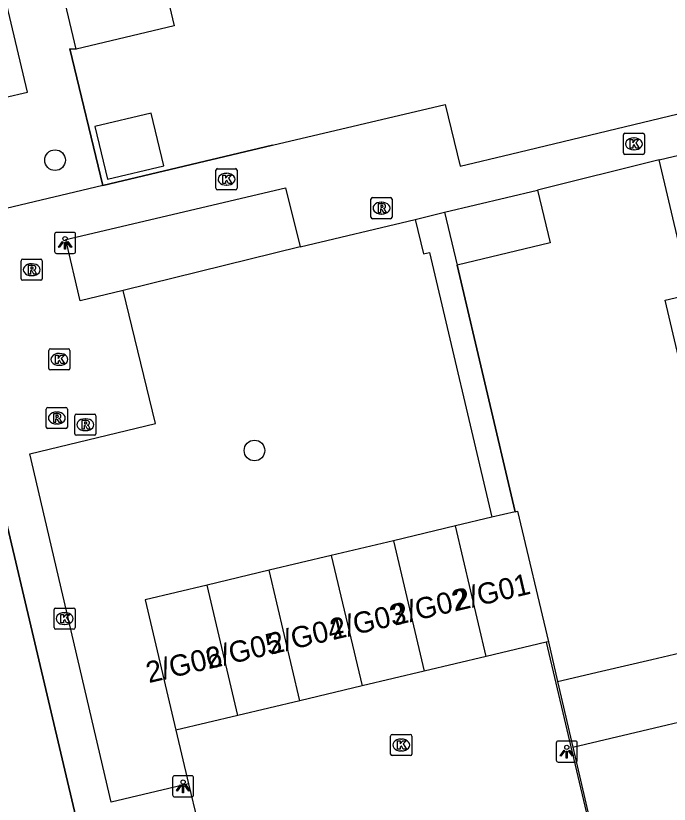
# Model space of a CAD drawing. Extents: x 157663 to 158496, y 379212 to 380934.
# Drawn here: x 158321.09 to 158352, y 380744.87 to 380782.15 of the extents above; entities that cross this region are included whole.
import ezdxf

# ---------------------------------------------------------------- set-up
doc = ezdxf.new("R2010")
doc.units = 0
for name, color, linetype in [('IMGEO_Boom', 7, 'Continuous'), ('IMGEO_Groenvoorziening', 7, 'Continuous'), ('IMGEO_Hek', 7, 'Continuous'), ('IMGEO_Kolk', 7, 'Continuous'), ('IMGEO_Lichtpunt', 7, 'Continuous'), ('IMGEO_Muur', 7, 'Continuous'), ('IMGEO_Pand', 7, 'Continuous'), ('IMGEO_Pand_nummerreeks', 7, 'Continuous'), ('IMGEO_Rijbaan_lokaal_open', 7, 'Continuous'), ('IMGEO_Rioolput', 7, 'Continuous'), ('IMGEO_Voetpad_open', 7, 'Continuous')]:
    doc.layers.add(name, color=color, linetype=linetype)

msp = doc.modelspace()

# ---------------------------------------------------------------- linework, layer by layer
at = {"layer": 'IMGEO_Boom'}
for centre in [(158322.952, 380775.321), (158332.384, 380761.593)]:
    msp.add_circle(centre, 0.489, dxfattribs=at)
at = {"layer": 'IMGEO_Groenvoorziening'}
for points in [[(158323.949, 380780.572), (158323.65, 380780.585), (158325.212, 380774.131)], [(158334.541, 380771.23), (158326.174, 380769.159)]]:
    msp.add_lwpolyline(points, dxfattribs=at)
at = {"layer": 'IMGEO_Hek'}
for points in [[(158325.212, 380774.131), (158323.65, 380780.585), (158323.949, 380780.572)], [(158341.41, 380777.959), (158342.116, 380775.038), (158344.495, 380775.601)], [(158333.237, 380776.03), (158325.212, 380774.131)], [(158314.918, 380732.983), (158325.994, 380735.514), (158319.98, 380760.991)]]:
    msp.add_lwpolyline(points, dxfattribs=at)
at = {"layer": 'IMGEO_Kolk'}
for p, q in [((158349.832, 380775.666), (158349.832, 380776.518)), ((158349.907, 380776.592), (158350.759, 380776.592)), ((158350.833, 380776.518), (158350.833, 380775.666)), ((158350.32, 380776.372), (158350.345, 380776.372)), ((158350.343, 380775.812), (158350.318, 380775.812)), ((158350.759, 380775.592), (158349.907, 380775.592)), ((158330.562, 380773.994), (158330.562, 380774.846)), ((158330.637, 380774.92), (158331.489, 380774.92)), ((158331.05, 380774.7), (158331.075, 380774.7)), ((158331.563, 380774.846), (158331.563, 380773.994)), ((158331.489, 380773.92), (158330.637, 380773.92)), ((158331.073, 380774.14), (158331.048, 380774.14)), ((158322.655, 380765.476), (158322.655, 380766.328)), ((158322.73, 380766.402), (158323.582, 380766.402)), ((158323.143, 380766.182), (158323.168, 380766.182)), ((158323.656, 380766.328), (158323.656, 380765.476)), ((158323.582, 380765.402), (158322.73, 380765.402)), ((158323.166, 380765.622), (158323.141, 380765.622)), ((158322.98, 380754.145), (158323.832, 380754.145)), ((158322.905, 380753.219), (158322.905, 380754.071)), ((158323.393, 380753.925), (158323.418, 380753.925)), ((158323.906, 380754.071), (158323.906, 380753.219)), ((158323.832, 380753.145), (158322.98, 380753.145)), ((158323.416, 380753.365), (158323.391, 380753.365)), ((158338.9, 380748.167), (158339.752, 380748.167)), ((158338.825, 380747.241), (158338.825, 380748.093)), ((158339.313, 380747.947), (158339.338, 380747.947)), ((158339.826, 380748.093), (158339.826, 380747.241)), ((158339.752, 380747.167), (158338.9, 380747.167)), ((158339.336, 380747.387), (158339.311, 380747.387))]:
    msp.add_line(p, q, dxfattribs=at)
for points in [[(158349.832, 380775.666), (158349.832, 380776.518)], [(158349.907, 380776.592), (158350.759, 380776.592)], [(158350.833, 380776.518), (158350.833, 380775.666)], [(158350.153, 380776.292), (158350.276, 380776.292), (158350.276, 380776.141), (158350.406, 380776.292), (158350.57, 380776.292), (158350.424, 380776.141), (158350.577, 380775.892), (158350.425, 380775.892), (158350.34, 380776.056), (158350.276, 380775.989), (158350.276, 380775.892), (158350.153, 380775.892), (158350.153, 380776.292)], [(158350.759, 380775.592), (158349.907, 380775.592)], [(158330.562, 380773.994), (158330.562, 380774.846)], [(158330.637, 380774.92), (158331.489, 380774.92)], [(158331.563, 380774.846), (158331.563, 380773.994)], [(158330.883, 380774.62), (158331.006, 380774.62), (158331.006, 380774.469), (158331.136, 380774.62), (158331.3, 380774.62), (158331.154, 380774.469), (158331.307, 380774.22), (158331.155, 380774.22), (158331.07, 380774.384), (158331.006, 380774.317), (158331.006, 380774.22), (158330.883, 380774.22), (158330.883, 380774.62)], [(158331.489, 380773.92), (158330.637, 380773.92)], [(158322.655, 380765.476), (158322.655, 380766.328)], [(158322.73, 380766.402), (158323.582, 380766.402)], [(158322.976, 380766.102), (158323.099, 380766.102), (158323.099, 380765.951), (158323.229, 380766.102), (158323.393, 380766.102), (158323.247, 380765.951), (158323.4, 380765.702), (158323.248, 380765.702), (158323.163, 380765.866), (158323.099, 380765.799), (158323.099, 380765.702), (158322.976, 380765.702), (158322.976, 380766.102)], [(158323.656, 380766.328), (158323.656, 380765.476)], [(158323.582, 380765.402), (158322.73, 380765.402)], [(158322.98, 380754.145), (158323.832, 380754.145)], [(158322.905, 380753.219), (158322.905, 380754.071)], [(158323.226, 380753.845), (158323.349, 380753.845), (158323.349, 380753.694), (158323.479, 380753.845), (158323.643, 380753.845), (158323.497, 380753.694), (158323.65, 380753.445), (158323.498, 380753.445), (158323.413, 380753.609), (158323.349, 380753.542), (158323.349, 380753.445), (158323.226, 380753.445), (158323.226, 380753.845)], [(158323.906, 380754.071), (158323.906, 380753.219)], [(158323.832, 380753.145), (158322.98, 380753.145)], [(158338.9, 380748.167), (158339.752, 380748.167)], [(158338.825, 380747.241), (158338.825, 380748.093)], [(158339.146, 380747.867), (158339.269, 380747.867), (158339.269, 380747.716), (158339.399, 380747.867), (158339.563, 380747.867), (158339.417, 380747.716), (158339.57, 380747.467), (158339.418, 380747.467), (158339.333, 380747.631), (158339.269, 380747.564), (158339.269, 380747.467), (158339.146, 380747.467), (158339.146, 380747.867)], [(158339.826, 380748.093), (158339.826, 380747.241)], [(158339.752, 380747.167), (158338.9, 380747.167)]]:
    msp.add_lwpolyline(points, dxfattribs=at)
for centre, start, end in [((158349.909, 380776.516), 91.552, 178.448), ((158349.909, 380776.516), 91.552, 178.448), ((158350.757, 380776.516), 1.552, 88.448), ((158350.757, 380776.516), 1.552, 88.448), ((158349.909, 380775.668), 181.552, 268.448), ((158349.909, 380775.668), 181.552, 268.448), ((158350.757, 380775.668), 271.552, 358.448), ((158350.757, 380775.668), 271.552, 358.448), ((158330.639, 380774.844), 91.552, 178.448), ((158330.639, 380774.844), 91.552, 178.448), ((158331.487, 380774.844), 1.552, 88.448), ((158331.487, 380774.844), 1.552, 88.448), ((158330.639, 380773.996), 181.552, 268.448), ((158330.639, 380773.996), 181.552, 268.448), ((158331.487, 380773.996), 271.552, 358.448), ((158331.487, 380773.996), 271.552, 358.448), ((158322.732, 380766.326), 91.552, 178.448), ((158322.732, 380766.326), 91.552, 178.448), ((158323.58, 380766.326), 1.552, 88.448), ((158323.58, 380766.326), 1.552, 88.448), ((158322.732, 380765.478), 181.552, 268.448), ((158322.732, 380765.478), 181.552, 268.448), ((158323.58, 380765.478), 271.552, 358.448), ((158323.58, 380765.478), 271.552, 358.448), ((158322.982, 380754.069), 91.552, 178.448), ((158322.982, 380754.069), 91.552, 178.448), ((158323.83, 380754.069), 1.552, 88.448), ((158323.83, 380754.069), 1.552, 88.448), ((158322.982, 380753.221), 181.552, 268.448), ((158322.982, 380753.221), 181.552, 268.448), ((158323.83, 380753.221), 271.552, 358.448), ((158323.83, 380753.221), 271.552, 358.448), ((158338.902, 380748.091), 91.552, 178.448), ((158338.902, 380748.091), 91.552, 178.448), ((158339.75, 380748.091), 1.552, 88.448), ((158339.75, 380748.091), 1.552, 88.448), ((158338.902, 380747.243), 181.552, 268.448), ((158338.902, 380747.243), 181.552, 268.448), ((158339.75, 380747.243), 271.552, 358.448), ((158339.75, 380747.243), 271.552, 358.448)]:
    msp.add_arc(centre, 0.0765, start, end, dxfattribs=at)
for centre, major_axis, ratio, start_param, end_param in [((158350.319, 380776.092), (-0.387, 0.002), 0.722429, 4.712389, 7.853982), ((158350.344, 380776.092), (-0.39, 0.002), 0.717154, 1.570796, 4.712389), ((158331.049, 380774.42), (-0.387, 0.002), 0.722429, 4.712389, 7.853982), ((158331.074, 380774.42), (-0.39, 0.002), 0.717154, 1.570796, 4.712389), ((158323.142, 380765.902), (-0.387, 0.002), 0.722429, 4.712389, 7.853982), ((158323.167, 380765.902), (-0.39, 0.002), 0.717154, 1.570796, 4.712389), ((158323.392, 380753.645), (-0.387, 0.002), 0.722429, 4.712389, 7.853982), ((158323.417, 380753.645), (-0.39, 0.002), 0.717154, 1.570796, 4.712389), ((158339.312, 380747.667), (-0.387, 0.002), 0.722429, 4.712389, 7.853982), ((158339.337, 380747.667), (-0.39, 0.002), 0.717154, 1.570796, 4.712389)]:
    msp.add_ellipse(centre, major_axis=major_axis, ratio=ratio, start_param=start_param, end_param=end_param, dxfattribs=at)
at = {"layer": 'IMGEO_Lichtpunt'}
for p, q in [((158322.927, 380771.814), (158322.927, 380771.007)), ((158322.927, 380771.814), (158322.927, 380771.007)), ((158323.829, 380771.909), (158323.021, 380771.909)), ((158323.829, 380771.909), (158323.021, 380771.909)), ((158323.923, 380771.007), (158323.923, 380771.814)), ((158323.923, 380771.007), (158323.923, 380771.814)), ((158323.021, 380770.913), (158323.829, 380770.913)), ((158323.021, 380770.913), (158323.829, 380770.913)), ((158347.559, 380747.854), (158346.751, 380747.854)), ((158347.559, 380747.854), (158346.751, 380747.854)), ((158346.657, 380747.759), (158346.657, 380746.952)), ((158346.657, 380747.759), (158346.657, 380746.952)), ((158347.653, 380746.952), (158347.653, 380747.759)), ((158347.653, 380746.952), (158347.653, 380747.759)), ((158346.751, 380746.858), (158347.559, 380746.858)), ((158346.751, 380746.858), (158347.559, 380746.858)), ((158328.51, 380746.117), (158328.51, 380745.31)), ((158328.51, 380746.117), (158328.51, 380745.31)), ((158329.412, 380746.212), (158328.604, 380746.212)), ((158329.412, 380746.212), (158328.604, 380746.212)), ((158329.506, 380745.31), (158329.506, 380746.117)), ((158329.506, 380745.31), (158329.506, 380746.117)), ((158328.604, 380745.216), (158329.412, 380745.216)), ((158328.604, 380745.216), (158329.412, 380745.216))]:
    msp.add_line(p, q, dxfattribs=at)
for points in [[(158323.301, 380771.478), (158323.34, 380771.45), (158323.152, 380771.188), (158323.114, 380771.215), (158323.301, 380771.478)], [(158323.403, 380771.43), (158323.45, 380771.43), (158323.45, 380771.108), (158323.403, 380771.108), (158323.403, 380771.43)], [(158323.513, 380771.45), (158323.551, 380771.477), (158323.738, 380771.215), (158323.699, 380771.187), (158323.513, 380771.45)], [(158347.031, 380747.423), (158347.07, 380747.395), (158346.882, 380747.133), (158346.844, 380747.16), (158347.031, 380747.423)], [(158347.243, 380747.395), (158347.281, 380747.422), (158347.468, 380747.16), (158347.429, 380747.132), (158347.243, 380747.395)], [(158347.133, 380747.375), (158347.18, 380747.375), (158347.18, 380747.053), (158347.133, 380747.053), (158347.133, 380747.375)], [(158328.884, 380745.781), (158328.923, 380745.753), (158328.735, 380745.491), (158328.697, 380745.518), (158328.884, 380745.781)], [(158328.986, 380745.733), (158329.033, 380745.733), (158329.033, 380745.411), (158328.986, 380745.411), (158328.986, 380745.733)], [(158329.096, 380745.753), (158329.134, 380745.78), (158329.321, 380745.518), (158329.282, 380745.49), (158329.096, 380745.753)]]:
    msp.add_lwpolyline(points, dxfattribs=at)
for centre in [(158323.426, 380771.612), (158347.156, 380747.557), (158329.009, 380745.915)]:
    msp.add_circle(centre, 0.0994, dxfattribs=at)
for centre, start, end in [((158323.021, 380771.814), 90, 180), ((158323.021, 380771.814), 90, 180), ((158323.829, 380771.814), 0, 90), ((158323.829, 380771.814), 0, 90), ((158323.021, 380771.007), 180, 270), ((158323.021, 380771.007), 180, 270), ((158323.829, 380771.007), 270, 0), ((158323.829, 380771.007), 270, 360), ((158346.751, 380747.759), 90, 180), ((158346.751, 380747.759), 90, 180), ((158347.559, 380747.759), 0, 90), ((158347.559, 380747.759), 0, 90), ((158346.751, 380746.952), 180, 270), ((158346.751, 380746.952), 180, 270), ((158347.559, 380746.952), 270, 0), ((158347.559, 380746.952), 270, 360), ((158328.604, 380746.117), 90, 180), ((158328.604, 380746.117), 90, 180), ((158329.412, 380746.117), 0, 90), ((158329.412, 380746.117), 0, 90), ((158328.604, 380745.31), 180, 270), ((158328.604, 380745.31), 180, 270), ((158329.412, 380745.31), 270, 0), ((158329.412, 380745.31), 270, 360)]:
    msp.add_arc(centre, 0.0946, start, end, dxfattribs=at)
at = {"layer": 'IMGEO_Muur'}
for points in [[(158333.237, 380776.03), (158341.41, 380777.959)], [(158351.526, 380775.342), (158345.772, 380773.91)], [(158344.716, 380758.699), (158341.972, 380770.361)], [(158346.181, 380752.523), (158353.297, 380722.372)]]:
    msp.add_lwpolyline(points, dxfattribs=at)
at = {"layer": 'IMGEO_Pand'}
for points in [[(158323.949, 380780.572), (158321.807, 380789.612)], [(158330.668, 380787.156), (158327.47, 380786.399), (158328.589, 380781.672), (158323.949, 380780.572)], [(158328.09, 380775.06), (158327.503, 380777.539), (158324.84, 380776.908), (158325.428, 380774.429), (158328.09, 380775.06)], [(158351.526, 380775.342), (158360.355, 380777.433)], [(158353.829, 380765.787), (158352.57, 380765.489), (158351.809, 380768.699), (158353.031, 380768.988), (158351.526, 380775.342)], [(158341.376, 380772.862), (158345.772, 380773.91)], [(158345.772, 380773.91), (158346.369, 380771.409), (158341.972, 380770.361)], [(158341.376, 380772.862), (158341.972, 380770.361)], [(158346.717, 380750.663), (158348.795, 380751.153), (158351.178, 380751.713), (158356.81, 380753.039), (158356.059, 380756.217), (158360.973, 380757.381), (158360.208, 380760.612)], [(158344.716, 380758.699), (158343.619, 380758.438)], [(158344.716, 380758.699), (158344.825, 380758.725), (158346.296, 380752.55)], [(158343.619, 380758.438), (158341.888, 380758.025)], [(158341.888, 380758.025), (158338.953, 380757.326)], [(158343.344, 380751.85), (158341.888, 380758.025)], [(158338.953, 380757.326), (158336.018, 380756.627)], [(158338.953, 380757.326), (158340.409, 380751.154)], [(158336.018, 380756.627), (158333.083, 380755.928)], [(158336.018, 380756.627), (158337.473, 380750.459)], [(158333.083, 380755.928), (158330.148, 380755.23)], [(158334.537, 380749.763), (158333.083, 380755.928)], [(158330.148, 380755.23), (158327.213, 380754.531), (158328.666, 380748.371)], [(158331.602, 380749.067), (158330.148, 380755.23)], [(158346.296, 380752.55), (158346.181, 380752.523), (158343.344, 380751.85)], [(158343.344, 380751.85), (158340.409, 380751.154)], [(158340.409, 380751.154), (158337.473, 380750.459)], [(158337.473, 380750.459), (158334.537, 380749.763)], [(158346.717, 380750.663), (158347.448, 380747.566)], [(158334.537, 380749.763), (158331.602, 380749.067)], [(158347.448, 380747.566), (158351.909, 380748.618), (158357.541, 380749.95)], [(158331.602, 380749.067), (158328.666, 380748.371)]]:
    msp.add_lwpolyline(points, dxfattribs=at)
at = {"layer": 'IMGEO_Rijbaan_lokaal_open'}
for points in [[(158346.296, 380752.55), (158346.717, 380750.663)], [(158328.666, 380748.371), (158329.261, 380745.828)], [(158347.448, 380747.566), (158353.297, 380722.372), (158355.983, 380711.227)], [(158329.261, 380745.828), (158329.69, 380744.059), (158326.028, 380743.217), (158326.478, 380741.304)]]:
    msp.add_lwpolyline(points, dxfattribs=at)
at = {"layer": 'IMGEO_Rioolput'}
for p, q in [((158337.968, 380773.554), (158338.82, 380773.554)), ((158337.893, 380772.628), (158337.893, 380773.48)), ((158338.381, 380773.334), (158338.406, 380773.334)), ((158338.894, 380773.48), (158338.894, 380772.628)), ((158338.404, 380772.774), (158338.379, 380772.774)), ((158338.82, 380772.554), (158337.968, 380772.554)), ((158321.348, 380769.716), (158321.348, 380770.568)), ((158321.423, 380770.642), (158322.275, 380770.642)), ((158322.349, 380770.568), (158322.349, 380769.716)), ((158321.836, 380770.422), (158321.861, 380770.422)), ((158321.859, 380769.862), (158321.834, 380769.862)), ((158322.275, 380769.642), (158321.423, 380769.642)), ((158322.535, 380762.703), (158322.535, 380763.555)), ((158322.61, 380763.629), (158323.462, 380763.629)), ((158323.536, 380763.555), (158323.536, 380762.703)), ((158323.023, 380763.409), (158323.048, 380763.409)), ((158323.884, 380762.386), (158323.884, 380763.238)), ((158323.959, 380763.312), (158324.811, 380763.312)), ((158324.372, 380763.092), (158324.397, 380763.092)), ((158324.885, 380763.238), (158324.885, 380762.386)), ((158323.046, 380762.849), (158323.021, 380762.849)), ((158323.462, 380762.629), (158322.61, 380762.629)), ((158324.395, 380762.532), (158324.37, 380762.532)), ((158324.811, 380762.312), (158323.959, 380762.312))]:
    msp.add_line(p, q, dxfattribs=at)
for points in [[(158337.968, 380773.554), (158338.82, 380773.554)], [(158337.893, 380772.628), (158337.893, 380773.48)], [(158338.482, 380773.252), (158338.23, 380773.254), (158338.23, 380772.854)], [(158338.408, 380773.173), (158338.354, 380773.173), (158338.354, 380773.092)], [(158338.894, 380773.48), (158338.894, 380772.628)], [(158338.23, 380772.854), (158338.354, 380772.854), (158338.354, 380773.016), (158338.365, 380773.016)], [(158338.354, 380773.092), (158338.406, 380773.092)], [(158338.412, 380772.987), (158338.483, 380772.854), (158338.623, 380772.854), (158338.558, 380772.98)], [(158338.82, 380772.554), (158337.968, 380772.554)], [(158321.348, 380769.716), (158321.348, 380770.568)], [(158321.423, 380770.642), (158322.275, 380770.642)], [(158322.349, 380770.568), (158322.349, 380769.716)], [(158321.937, 380770.34), (158321.685, 380770.342), (158321.685, 380769.942)], [(158321.863, 380770.261), (158321.809, 380770.261), (158321.809, 380770.18)], [(158321.809, 380770.18), (158321.861, 380770.18)], [(158321.685, 380769.942), (158321.809, 380769.942), (158321.809, 380770.104), (158321.82, 380770.104)], [(158321.867, 380770.075), (158321.938, 380769.942), (158322.078, 380769.942), (158322.013, 380770.068)], [(158322.275, 380769.642), (158321.423, 380769.642)], [(158322.535, 380762.703), (158322.535, 380763.555)], [(158322.61, 380763.629), (158323.462, 380763.629)], [(158323.536, 380763.555), (158323.536, 380762.703)], [(158323.124, 380763.327), (158322.872, 380763.329), (158322.872, 380762.929)], [(158322.872, 380762.929), (158322.996, 380762.929), (158322.996, 380763.091), (158323.007, 380763.091)], [(158323.05, 380763.248), (158322.996, 380763.248), (158322.996, 380763.167)], [(158322.996, 380763.167), (158323.048, 380763.167)], [(158323.884, 380762.386), (158323.884, 380763.238)], [(158323.959, 380763.312), (158324.811, 380763.312)], [(158324.885, 380763.238), (158324.885, 380762.386)], [(158323.054, 380763.062), (158323.125, 380762.929), (158323.265, 380762.929), (158323.2, 380763.055)], [(158324.473, 380763.01), (158324.221, 380763.012), (158324.221, 380762.612)], [(158324.221, 380762.612), (158324.345, 380762.612), (158324.345, 380762.774), (158324.356, 380762.774)], [(158324.399, 380762.931), (158324.345, 380762.931), (158324.345, 380762.85)], [(158324.345, 380762.85), (158324.397, 380762.85)], [(158324.403, 380762.745), (158324.474, 380762.612), (158324.614, 380762.612), (158324.549, 380762.738)], [(158323.462, 380762.629), (158322.61, 380762.629)], [(158324.811, 380762.312), (158323.959, 380762.312)]]:
    msp.add_lwpolyline(points, dxfattribs=at)
for centre, radius, start, end in [((158337.97, 380773.478), 0.0765, 91.552, 178.448), ((158337.97, 380773.478), 0.0765, 91.552, 178.448), ((158338.818, 380773.478), 0.0765, 1.552, 88.448), ((158338.818, 380773.478), 0.0765, 1.552, 88.448), ((158338.414, 380773.077), 0.0964, 77.0061, 93.1865), ((158338.428, 380773.134), 0.0378, 276.6634, 79.6772), ((158338.481, 380773.142), 0.109, 350.3612, 89.416), ((158338.364, 380772.963), 0.0533, 26.0293, 88.6989), ((158338.39, 380773.281), 0.19, 274.7715, 282.9687), ((158338.479, 380773.142), 0.112, 277.5842, 350.9817), ((158338.463, 380772.927), 0.108, 29.5134, 73.7905), ((158337.97, 380772.63), 0.0765, 181.552, 268.448), ((158337.97, 380772.63), 0.0765, 181.552, 268.448), ((158338.818, 380772.63), 0.0765, 271.552, 358.448), ((158338.818, 380772.63), 0.0765, 271.552, 358.448), ((158321.425, 380770.566), 0.0765, 91.552, 178.448), ((158321.425, 380770.566), 0.0765, 91.552, 178.448), ((158322.273, 380770.566), 0.0765, 1.552, 88.448), ((158322.273, 380770.566), 0.0765, 1.552, 88.448), ((158321.845, 380770.369), 0.19, 274.7715, 282.9687), ((158321.869, 380770.165), 0.0964, 77.0061, 93.1865), ((158321.883, 380770.222), 0.0378, 276.6634, 79.6772), ((158321.936, 380770.23), 0.109, 350.3612, 89.416), ((158321.934, 380770.23), 0.112, 277.5842, 350.9817), ((158321.819, 380770.051), 0.0533, 26.0293, 88.6989), ((158321.918, 380770.015), 0.108, 29.5134, 73.7905), ((158321.425, 380769.718), 0.0765, 181.552, 268.448), ((158321.425, 380769.718), 0.0765, 181.552, 268.448), ((158322.273, 380769.718), 0.0765, 271.552, 358.448), ((158322.273, 380769.718), 0.0765, 271.552, 358.448), ((158322.612, 380763.553), 0.0765, 91.552, 178.448), ((158322.612, 380763.553), 0.0765, 91.552, 178.448), ((158323.46, 380763.553), 0.0765, 1.552, 88.448), ((158323.46, 380763.553), 0.0765, 1.552, 88.448), ((158323.006, 380763.038), 0.0533, 26.0293, 88.6989), ((158323.032, 380763.356), 0.19, 274.7715, 282.9687), ((158323.056, 380763.152), 0.0964, 77.0061, 93.1865), ((158323.07, 380763.209), 0.0378, 276.6634, 79.6772), ((158323.123, 380763.217), 0.109, 350.3612, 89.416), ((158323.121, 380763.217), 0.112, 277.5842, 350.9817), ((158323.105, 380763.002), 0.108, 29.5134, 73.7905), ((158323.961, 380763.236), 0.0765, 91.552, 178.448), ((158323.961, 380763.236), 0.0765, 91.552, 178.448), ((158324.809, 380763.236), 0.0765, 1.552, 88.448), ((158324.809, 380763.236), 0.0765, 1.552, 88.448), ((158322.612, 380762.705), 0.0765, 181.552, 268.448), ((158322.612, 380762.705), 0.0765, 181.552, 268.448), ((158323.46, 380762.705), 0.0765, 271.552, 358.448), ((158323.46, 380762.705), 0.0765, 271.552, 358.448), ((158324.355, 380762.721), 0.0533, 26.0293, 88.6989), ((158324.381, 380763.039), 0.19, 274.7715, 282.9687), ((158324.405, 380762.835), 0.0964, 77.0061, 93.1865), ((158324.419, 380762.892), 0.0378, 276.6634, 79.6772), ((158324.472, 380762.9), 0.109, 350.3612, 89.416), ((158324.47, 380762.9), 0.112, 277.5842, 350.9817), ((158324.454, 380762.685), 0.108, 29.5134, 73.7905), ((158323.961, 380762.388), 0.0765, 181.552, 268.448), ((158323.961, 380762.388), 0.0765, 181.552, 268.448), ((158324.809, 380762.388), 0.0765, 271.552, 358.448), ((158324.809, 380762.388), 0.0765, 271.552, 358.448)]:
    msp.add_arc(centre, radius, start, end, dxfattribs=at)
for centre, major_axis, ratio, start_param, end_param in [((158338.38, 380773.054), (-0.387, 0.002), 0.722429, 4.712389, 7.853982), ((158338.405, 380773.054), (-0.39, 0.002), 0.717154, 1.570796, 4.712389), ((158321.835, 380770.142), (-0.387, 0.002), 0.722429, 4.712389, 7.853982), ((158321.86, 380770.142), (-0.39, 0.002), 0.717154, 1.570796, 4.712389), ((158323.022, 380763.129), (-0.387, 0.002), 0.722429, 4.712389, 7.853982), ((158323.047, 380763.129), (-0.39, 0.002), 0.717154, 1.570796, 4.712389), ((158324.371, 380762.812), (-0.387, 0.002), 0.722429, 4.712389, 7.853982), ((158324.396, 380762.812), (-0.39, 0.002), 0.717154, 1.570796, 4.712389)]:
    msp.add_ellipse(centre, major_axis=major_axis, ratio=ratio, start_param=start_param, end_param=end_param, dxfattribs=at)
at = {"layer": 'IMGEO_Voetpad_open'}
for points in [[(158325.212, 380774.131), (158320.643, 380773.037), (158319.462, 380778.03), (158321.652, 380778.544), (158318.689, 380791.013), (158311.684, 380789.335), (158308.853, 380801.397)], [(158325.212, 380774.131), (158333.237, 380776.03), (158341.41, 380777.959), (158342.116, 380775.038), (158344.495, 380775.601), (158371.565, 380782.109)], [(158351.526, 380775.342), (158345.772, 380773.91)], [(158326.174, 380769.159), (158324.144, 380768.675), (158323.462, 380771.566), (158333.854, 380774.011), (158334.541, 380771.23)], [(158339.991, 380772.517), (158341.376, 380772.862)], [(158334.541, 380771.23), (158339.991, 380772.517)], [(158339.991, 380772.517), (158340.376, 380770.887), (158340.659, 380770.949), (158343.619, 380758.438)], [(158341.972, 380770.361), (158344.716, 380758.699)], [(158329.261, 380745.828), (158325.607, 380744.965), (158321.753, 380761.44), (158327.709, 380762.878), (158326.174, 380769.159)], [(158308.977, 380758.404), (158319.98, 380760.991), (158325.994, 380735.514), (158314.918, 380732.983)]]:
    msp.add_lwpolyline(points, dxfattribs=at)

# ---------------------------------------------------------------- texts
at = {"layer": 'IMGEO_Pand_nummerreeks'}
for s, p in [('2/G01', (158341.953, 380753.999)), ('2/G02', (158339.019, 380753.312)), ('2/G03', (158336.084, 380752.625)), ('2/G04', (158333.149, 380751.938)), ('2/G05', (158330.208, 380751.25)), ('2/G06', (158327.386, 380750.59))]:
    msp.add_text(s, height=1, rotation=13.171, dxfattribs=at).set_placement(p)

doc.saveas('drawing.dxf')
